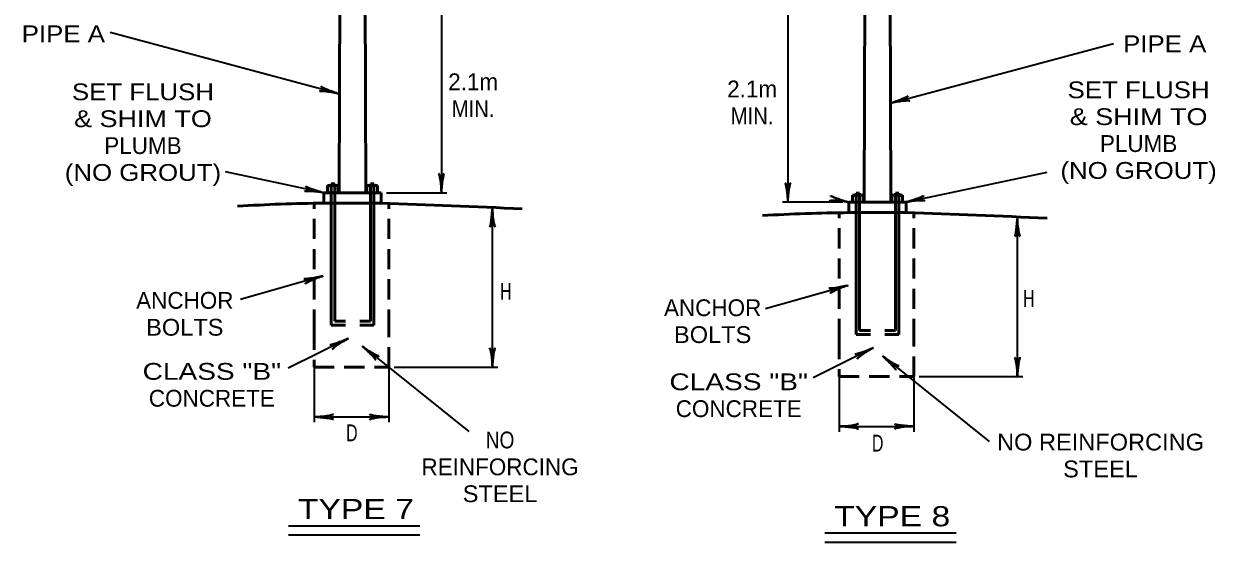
# Model space of a CAD drawing. Extents: x -274 to 582, y -298 to 246.
# Drawn here: x -64.7 to 148.2, y 7.6 to 100.2 of the extents above; entities that cross this region are included whole.
import ezdxf
from ezdxf.enums import TextEntityAlignment as Align

# ---------------------------------------------------------------- set-up
doc = ezdxf.new("R2010")
doc.units = 0
doc.header["$LTSCALE"] = 1.2
doc.linetypes.add('MEDIUM_DASHED', pattern=[4.5, 3, -1.5])
doc.layers.add('1', color=7, linetype='Continuous', lineweight=53)

msp = doc.modelspace()

# ---------------------------------------------------------------- linework, layer by layer
at = {"layer": '1'}
for p, q in [((85.718, 164.563), (85.452, 68.332)), ((89.842, 164.563), (90.241, 68.332)), ((-8.14, 143.838), (-8.345, 70.015)), ((-3.862, 143.838), (-3.556, 70.015)), ((-10.421, 70.015), (-10.421, 71.293)), ((-10.421, 71.293), (-8.505, 71.293)), ((-9.878, 71.293), (-9.878, 71.389)), ((-9.878, 71.389), (-9.048, 71.389)), ((-9.783, 71.612), (-9.144, 71.612)), ((-9.783, 71.389), (-9.783, 71.612)), ((-9.783, 46.382), (-9.783, 71.293)), ((-9.144, 71.389), (-9.144, 71.612)), ((-9.144, 47.108), (-9.144, 71.293)), ((-9.048, 71.293), (-9.048, 71.389)), ((-8.505, 70.015), (-8.505, 71.293)), ((-3.396, 71.293), (-1.48, 71.293)), ((-3.396, 70.015), (-3.396, 71.293)), ((-2.853, 71.293), (-2.853, 71.389)), ((-2.853, 71.389), (-2.023, 71.389)), ((-2.758, 71.612), (-2.119, 71.612)), ((-2.758, 71.389), (-2.758, 71.612)), ((-2.758, 47.108), (-2.758, 71.293)), ((-2.119, 71.389), (-2.119, 71.612)), ((-2.119, 46.382), (-2.119, 71.293)), ((-2.023, 71.293), (-2.023, 71.389)), ((-1.48, 70.015), (-1.48, 71.293)), ((-11.06, 70.015), (-0.841, 70.015)), ((-11.06, 70.015), (-11.06, 68.154)), ((-11.06, 68.154), (-0.841, 68.154)), ((-0.841, 70.015), (-0.841, 68.154)), ((82.737, 68.332), (92.956, 68.332)), ((82.737, 68.332), (82.737, 66.471)), ((83.376, 68.332), (83.376, 69.61)), ((83.376, 69.61), (85.292, 69.61)), ((83.919, 69.61), (83.919, 69.706)), ((83.919, 69.706), (84.749, 69.706)), ((84.015, 69.929), (84.654, 69.929)), ((84.015, 69.706), (84.015, 69.929)), ((84.015, 44.699), (84.015, 69.61)), ((84.654, 69.706), (84.654, 69.929)), ((84.654, 45.425), (84.654, 69.61)), ((84.749, 69.61), (84.749, 69.706)), ((85.292, 68.332), (85.292, 69.61)), ((90.401, 69.61), (92.317, 69.61)), ((90.401, 68.332), (90.401, 69.61)), ((90.944, 69.61), (90.944, 69.706)), ((90.944, 69.706), (91.774, 69.706)), ((91.04, 69.929), (91.679, 69.929)), ((91.04, 69.706), (91.04, 69.929)), ((91.04, 45.425), (91.04, 69.61)), ((91.679, 69.706), (91.679, 69.929)), ((91.679, 44.699), (91.679, 69.61)), ((91.774, 69.61), (91.774, 69.706)), ((92.317, 68.332), (92.317, 69.61)), ((92.956, 68.332), (92.956, 66.471)), ((82.737, 66.471), (92.956, 66.471)), ((-9.144, 47.108), (-7.227, 47.108)), ((-4.671, 47.108), (-2.758, 47.108)), ((-9.783, 46.382), (-7.227, 46.382)), ((-4.671, 46.382), (-2.119, 46.382)), ((84.654, 45.425), (86.57, 45.425)), ((89.126, 45.425), (91.04, 45.425)), ((84.015, 44.699), (86.57, 44.699)), ((89.126, 44.699), (91.679, 44.699))]:
    msp.add_line(p, q, dxfattribs=at)
at = {"layer": '1', "lineweight": 35}
for p, q in [((9.93, 105.611), (9.93, 70.015)), ((71.833, 103.928), (71.833, 68.332)), ((-8.374, 87.685), (-49.251, 98.636)), ((90.137, 86.002), (130.021, 96.687)), ((-11.06, 70.015), (-28.638, 73.744)), ((92.823, 68.332), (118.152, 73.705)), ((0.118, 70.015), (10.888, 70.015)), ((81.646, 68.332), (70.875, 68.332)), ((19.036, 38.859), (19.036, 67.348)), ((112.834, 37.176), (112.834, 65.665)), ((-11.22, 55.161), (-25.968, 50.963)), ((82.577, 53.478), (67.83, 49.28)), ((-6.713, 43.997), (-17.468, 38.67)), ((-4.2, 42.626), (14.85, 27.362)), ((87.084, 42.314), (76.33, 36.987)), ((88.721, 40.879), (107.77, 25.615)), ((-12.822, 38.859), (-12.822, 29.028)), ((0.514, 38.859), (0.514, 29.028)), ((1.473, 38.859), (19.995, 38.859)), ((80.975, 37.176), (80.975, 27.345)), ((94.311, 37.176), (94.311, 27.345)), ((95.27, 37.176), (113.792, 37.176)), ((-12.822, 29.986), (0.514, 29.986)), ((80.975, 28.303), (94.311, 28.303)), ((-17.419, 10.541), (6.054, 10.541)), ((-17.419, 8.902), (6.054, 8.902)), ((78.41, 9.258), (101.883, 9.258)), ((78.41, 7.62), (101.883, 7.62))]:
    msp.add_line(p, q, dxfattribs=at)
at = {"layer": '1', "linetype": 'MEDIUM_DASHED'}
for p, q in [((-12.822, 45.57), (-12.822, 68.136)), ((0.514, 45.57), (0.514, 68.112)), ((80.975, 43.887), (80.975, 66.453)), ((94.311, 43.887), (94.311, 66.429))]:
    msp.add_line(p, q, dxfattribs=at)
for points in [[(-12.822, 45.57), (-12.822, 38.859), (0.514, 38.859), (0.514, 45.57)], [(-12.822, 45.57), (-12.822, 38.859), (0.514, 38.859), (0.514, 45.57)], [(80.975, 43.887), (80.975, 37.176), (94.311, 37.176), (94.311, 43.887)], [(80.975, 43.887), (80.975, 37.176), (94.311, 37.176), (94.311, 43.887)]]:
    msp.add_lwpolyline(points, dxfattribs=at)
at = {"layer": '1'}
for centre, radius, start, end in [((-8.599, -228.256), 296.421, 90.47573, 93.46734), ((-39.901, -1210.456), 1279.207, 87.12083, 88.25023), ((85.198, -229.939), 296.421, 90.47573, 93.46734), ((53.896, -1212.139), 1279.207, 87.12083, 88.25023)]:
    msp.add_arc(centre, radius, start, end, dxfattribs=at)
at = {"layer": '1', "lineweight": 40}
for centre, major_axis, ratio, start_param, end_param in [((-9.725, 87.704), (2.118, -0.373), 0.122415, 0.8963533, 3.1415927), ((-9.607, 88.279), (1.981, -0.749), 0.07063, 3.1407148, 5.41811), ((91.37, 86.596), (-1.981, -0.749), 0.07063, 0.8650754, 3.1424706), ((91.37, 86.596), (-1.981, -0.749), 0.07063, 0.8650754, 3.1424706), ((91.488, 86.021), (-2.118, -0.373), 0.122415, 3.1415927, 5.386832), ((91.488, 86.021), (-2.118, -0.373), 0.122415, 3.1415927, 5.386832), ((9.598, 71.324), (0.187, -2.143), 0.122415, 0.8963533, 3.1415927), ((10.184, 71.36), (-0.211, -2.108), 0.07063, 3.1407148, 5.41811), ((-12.41, 69.962), (2.135, -0.261), 0.122415, 0.8963533, 3.1415927), ((-12.323, 70.542), (2.018, -0.644), 0.07063, 3.1407148, 5.41811), ((71.579, 69.677), (0.211, -2.108), 0.07063, 0.8650754, 3.1424706), ((71.579, 69.677), (0.211, -2.108), 0.07063, 0.8650754, 3.1424706), ((72.165, 69.641), (-0.187, -2.143), 0.122415, 3.1415927, 5.386832), ((72.165, 69.641), (-0.187, -2.143), 0.122415, 3.1415927, 5.386832), ((81.387, 68.279), (2.135, -0.261), 0.122415, 0.8963533, 3.1415927), ((81.474, 68.859), (2.018, -0.644), 0.07063, 3.1407148, 5.41811), ((94.086, 68.859), (-2.018, -0.644), 0.07063, 0.8650754, 3.1424706), ((94.173, 68.279), (-2.135, -0.261), 0.122415, 3.1415927, 5.386832), ((18.782, 66.003), (0.211, 2.108), 0.07063, 3.1407148, 5.41811), ((19.368, 66.038), (-0.187, 2.143), 0.122415, 0.8963533, 3.1415927), ((112.58, 64.32), (0.211, 2.108), 0.07063, 3.1407148, 5.41811), ((112.58, 64.32), (0.211, 2.108), 0.07063, 3.1407148, 5.41811), ((113.165, 64.355), (-0.187, 2.143), 0.122415, 0.8963533, 3.1415927), ((113.165, 64.355), (-0.187, 2.143), 0.122415, 0.8963533, 3.1415927), ((-12.583, 55.037), (2.085, 0.374), 0.07063, 3.1407148, 5.41811), ((-12.583, 55.037), (2.085, 0.374), 0.07063, 3.1407148, 5.41811), ((-12.389, 54.484), (2.01, 0.767), 0.122415, 0.8963533, 3.1415927), ((-12.389, 54.484), (2.01, 0.767), 0.122415, 0.8963533, 3.1415927), ((81.214, 53.354), (2.085, 0.374), 0.07063, 3.1407148, 5.41811), ((81.214, 53.354), (2.085, 0.374), 0.07063, 3.1407148, 5.41811), ((81.409, 52.801), (2.01, 0.767), 0.122415, 0.8963533, 3.1415927), ((81.409, 52.801), (2.01, 0.767), 0.122415, 0.8963533, 3.1415927), ((-8.031, 43.627), (1.982, 0.747), 0.07063, 3.1407148, 5.41811), ((-8.031, 43.627), (1.982, 0.747), 0.07063, 3.1407148, 5.41811), ((-7.739, 43.118), (1.837, 1.119), 0.122415, 0.8963533, 3.1415927), ((-7.739, 43.118), (1.837, 1.119), 0.122415, 0.8963533, 3.1415927), ((-3.309, 41.587), (-1.513, 1.482), 0.07063, 3.1407148, 5.41811), ((-3.309, 41.587), (-1.513, 1.482), 0.07063, 3.1407148, 5.41811), ((-2.97, 42.066), (-1.789, 1.194), 0.122415, 0.8963533, 3.1415927), ((-2.97, 42.066), (-1.789, 1.194), 0.122415, 0.8963533, 3.1415927), ((18.705, 40.168), (0.187, -2.143), 0.122415, 0.8963533, 3.1415927), ((19.29, 40.204), (-0.211, -2.108), 0.07063, 3.1407148, 5.41811), ((85.766, 41.944), (1.982, 0.747), 0.07063, 3.1407148, 5.41811), ((85.766, 41.944), (1.982, 0.747), 0.07063, 3.1407148, 5.41811), ((86.058, 41.435), (1.837, 1.119), 0.122415, 0.8963533, 3.1415927), ((86.058, 41.435), (1.837, 1.119), 0.122415, 0.8963533, 3.1415927), ((89.612, 39.84), (-1.513, 1.482), 0.07063, 3.1407148, 5.41811), ((89.612, 39.84), (-1.513, 1.482), 0.07063, 3.1407148, 5.41811), ((89.95, 40.319), (-1.789, 1.194), 0.122415, 0.8963533, 3.1415927), ((89.95, 40.319), (-1.789, 1.194), 0.122415, 0.8963533, 3.1415927), ((112.502, 38.485), (0.187, -2.143), 0.122415, 0.8963533, 3.1415927), ((113.087, 38.521), (-0.211, -2.108), 0.07063, 3.1407148, 5.41811), ((-11.478, 29.732), (-2.108, 0.211), 0.07063, 3.1407148, 5.41811), ((-11.478, 29.732), (-2.108, 0.211), 0.07063, 3.1407148, 5.41811), ((-11.513, 30.318), (-2.143, -0.187), 0.122415, 0.8963533, 3.1415927), ((-11.513, 30.318), (-2.143, -0.187), 0.122415, 0.8963533, 3.1415927), ((-0.795, 29.655), (2.143, 0.187), 0.122415, 0.8963533, 3.1415927), ((-0.831, 30.24), (2.108, -0.211), 0.07063, 3.1407148, 5.41811), ((82.319, 28.049), (-2.108, 0.211), 0.07063, 3.1407148, 5.41811), ((82.319, 28.049), (-2.108, 0.211), 0.07063, 3.1407148, 5.41811), ((82.284, 28.635), (-2.143, -0.187), 0.122415, 0.8963533, 3.1415927), ((82.284, 28.635), (-2.143, -0.187), 0.122415, 0.8963533, 3.1415927), ((93.002, 27.972), (2.143, 0.187), 0.122415, 0.8963533, 3.1415927), ((93.002, 27.972), (2.143, 0.187), 0.122415, 0.8963533, 3.1415927), ((92.967, 28.557), (2.108, -0.211), 0.07063, 3.1407148, 5.41811), ((92.967, 28.557), (2.108, -0.211), 0.07063, 3.1407148, 5.41811)]:
    msp.add_ellipse(centre, major_axis=major_axis, ratio=ratio, start_param=start_param, end_param=end_param, dxfattribs=at)

# ---------------------------------------------------------------- texts
at = {"layer": '1'}
for s, width, p in [('PIPE A', 1.15, (-57.624, 96.905)), ('PIPE A', 1.15, (139.157, 95.121)), ('SET FLUSH', 1.15, (-43.397, 86.543)), ('SET FLUSH', 1.15, (134.493, 86.905)), ('MIN.', 0.9, (15.594, 83.538)), ('MIN.', 0.9, (65.439, 82.252)), ('& SHIM TO', 1.2, (134.493, 82.105)), ('& SHIM TO', 1.2, (-43.397, 81.743)), ('(NO GROUT)', 1.15, (-43.397, 72.143)), ('(NO GROUT)', 1.15, (134.493, 72.505)), ('H', 0.7, (21.439, 50.897)), ('H', 0.7, (114.87, 49.634)), ('BOLTS', 1.05, (-35.921, 44.499)), ('BOLTS', 1.05, (58.389, 43.185)), ('CLASS "B"', 1.25, (-31.089, 36.62)), ('CLASS "B"', 1.25, (63.044, 34.758)), ('D', 0.7, (-6.069, 25.642)), ('NO', 0.85, (20.404, 24.37)), ('D', 0.7, (87.884, 23.807)), ('NO REINFORCING', 1.05, (127.69, 23.993)), ('STEEL', 1.05, (127.69, 19.193)), ('STEEL', 1.05, (20.404, 14.77))]:
    msp.add_text(s, height=3, dxfattribs=dict(at, width=width)).set_placement(p, align=Align.CENTER)
for s, p in [('2.1m', (15.594, 88.338)), ('2.1m', (65.439, 87.052)), ('PLUMB', (-43.397, 76.943)), ('PLUMB', (134.493, 77.305)), ('ANCHOR', (-35.921, 49.299)), ('ANCHOR', (58.389, 47.985)), ('CONCRETE', (-31.089, 31.82)), ('CONCRETE', (63.044, 29.958)), ('REINFORCING', (20.403, 19.57))]:
    msp.add_text(s, height=3, dxfattribs=at).set_placement(p, align=Align.CENTER)
at = {"layer": '1', "width": 1.25}
for s, p in [('TYPE 7', (-15.722, 11.736)), ('TYPE 8', (80.107, 10.453))]:
    msp.add_text(s, height=3.6, dxfattribs=at).set_placement(p)

doc.saveas('drawing.dxf')
